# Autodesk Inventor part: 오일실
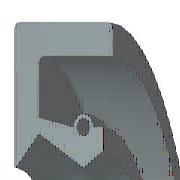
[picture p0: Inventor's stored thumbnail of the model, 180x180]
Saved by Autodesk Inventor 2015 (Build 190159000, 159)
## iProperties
Created: 2009-02
Part Number: 오일실
Material: 고무
Description: 오일-실
Document SubType Name: Modeling
Standard: KS B 2804
Designer: SeoGD™
Standards Organization: KS
Language: ko-KR
Size Designation: D - 10 20 7
Categories: <MemberInstance><Categories><Category DisplayName="샤프트 부품" InternalName="7f7aeb1f-a693-4053-b835-cee3144e0d98" Mnemonic="SHFT"><Category DisplayName="실링" Intern
Density: 0.93 g/cm^3
Appearance: 고무 - 검은색 - 버전 1.1
Mass: 1.11329 g
Surface Area: 16.3871 cm^2
Volume: 1.19708 cm^3
IsCustomPart: 0
Author: SeoGD™
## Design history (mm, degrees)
revolve "본체" stored, may be unused: angle "d17" = 90 deg
revolve "스프링1" stored, may be unused: angle "d18" = 90 deg
body "Solid1"
sketch "스케치1"
  geometry: L1 (0, 10)-(7, 10); L2 (7, 8.25)-(1.75, 8.25); L3 (1.75, 6.75)-(4.9, 5); L4 (4.9, 5)-(0, 5); L5 (0, 0)-(9.586, 0) reference; L6 (4.9, 5)-(6.3, 5.875); L7 (0, 18)-(0, -3) reference; L8 (-1.941, 0)-(11.507, 0) reference; L9 (4.2, 7.1)-(1.75, 7.59); L10 (1.75, 7.59)-(1.75, 8.25); L11 (0, 10)-(0, 5.088); L12 (4.9, 5)-(0, 5); L13 (1.75, 6.75)-(0.152, 5.028); L14 (7, 10)-(7, 8.25); L15 (5.6, 7.1)-(6.3, 7.1); L16 (6.3, 7.1)-(6.3, 5.875); C1 r 0.455 at (4.9, 7.1); A1 r 0.7 centre (4.9, 7.1) between (5.6, 7.1) and (4.2, 7.1); A2 r 0.088 centre (0.088, 5.088) between (0, 5.088) and (0.152, 5.028); 1 further point
  constraints: 28 end point, 5 horizontal alignment, 5 point on line, 4 point on circle, 4 vertical alignment, 3 centre point, 3 tangent, 2 collinear, 2 horizontal, 2 perpendicular, 1 coincident, 1 parallel
  dimensions: "d0" = 20 diameter of L1 L5 (= SD2); "d1" = 1.75 distance of L1.end L2.start (= SD); "d2" = 0.91 diameter of C1 (= SPDI); "d3" = 1.4 diameter of A1 (= SPDA); "d4" = 10 diameter of L3.end L5 (= NND); "d5" = 13.5 diameter of L3.start L5 (= TKDM); "d7" = 15.18 diameter of L9.end L5 (= TKDM + 0.24 x SWDT); "d8" = 1.75 distance between parallel lines of L11 L10 (= SD); "d9" = 4.9 distance from line of L11 C1.centre (= SPDST); "d10" = 14.2 diameter of C1.centre L5 (= HLDM); "d11" = 0.0875 radius of A2 (= 0.25 x LAB); "d12" = 6.3 distance between parallel lines of L11 L16 (= SDI); "d13" = 11.75 diameter of L6.end L5 (= ABDM); "d14" = 7 distance from line of L11 L1.end (= SWDT)
fillet "모깎기1" dims "d6" = 0.3 (= RR)
other parameters: "SD2" = 20 [user parameter; used in 1 equation term], "SWDT" = 7 [user parameter; used in 2 equation terms], "RR" = 0.3 [user parameter; used in 1 equation term], "SD" = 1.75 [user parameter; used in 2 equation terms], "NND" = 10 [user parameter; used in 1 equation term], "SPDA" = 1.4 [user parameter; used in 1 equation term], "SPDI" = 0.91 [user parameter; used in 1 equation term], "TKDM" = 13.5 [user parameter; used in 2 equation terms], "HLDM" = 14.2 [user parameter; used in 1 equation term], "ABDM" = 11.75 [user parameter; used in 1 equation term], "SDI" = 6.3 [user parameter; used in 1 equation term], "SPDST" = 4.9 [user parameter; used in 1 equation term], "LAB" = 0.35 [user parameter; used in 1 equation term], "d15" = 0, "d16" = 0, "d19" = 0
